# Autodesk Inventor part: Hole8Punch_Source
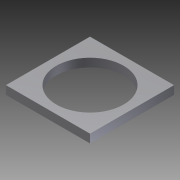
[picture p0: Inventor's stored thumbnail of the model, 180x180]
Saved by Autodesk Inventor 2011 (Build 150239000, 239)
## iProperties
Created: 2007-02
Part Number: Hole8Punch_Source
Material: Default
Document SubType Name: Sheet Metal
Designer: Autodesk, Inc.
Mass: 0.0497345 g
Surface Area: 1.64602 cm^2
Volume: 0.0497345 cm^3
Density: 1 g/cm^3
Sheet Metal Rule: 1 mm
Author: Autodesk, Inc.
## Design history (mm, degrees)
node "Face1"
  sketch "Sketch1"
    geometry: L1 (-5, 5)-(5, 5); L2 (5, 5)-(5, -5); L3 (5, -5)-(-5, -5); L4 (-5, -5)-(-5, 5); L5 (-5, 5)-(5, -5); 2 further points
    constraints: 10 end point, 2 parallel, 1 coincident, 1 horizontal, 1 midpoint, 1 perpendicular
    dimensions: "d0" = 10 distance of L2.end L3.end; "d1" = 10 distance of L1.end L2.end (= d0)
sketch "Sketch2"
  geometry: C1 r 4 at (0, 0); 2 further points
  constraints: 2 coincident, 1 centre point
  dimensions: "d3" = 8 diameter of C1
cut "Cut1" sketch "Sketch2" dims "d4" = 1 (= Thickness), "d5" = 0
body "Solid1"
face "Plate1" dims "Thickness" = 1
other parameters: "BendRadius" = 0.5, "BendReliefWidth" = 1 (= Thickness), "BendReliefDepth" = 0.5 (= 0.5 x Thickness), "CornerReliefSize" = 4 (= 4 x Thickness), "SeamGap" = 0.01, "MinimumRemnant" = 2 (= 2 x Thickness), "TransitionRadius" = 0.5 (= BendRadius), "JacobiRadiusSize" = 1 (= Thickness), "d2" = 0.5 (= BendRadius), "GapSize" = 1 (= Thickness)
